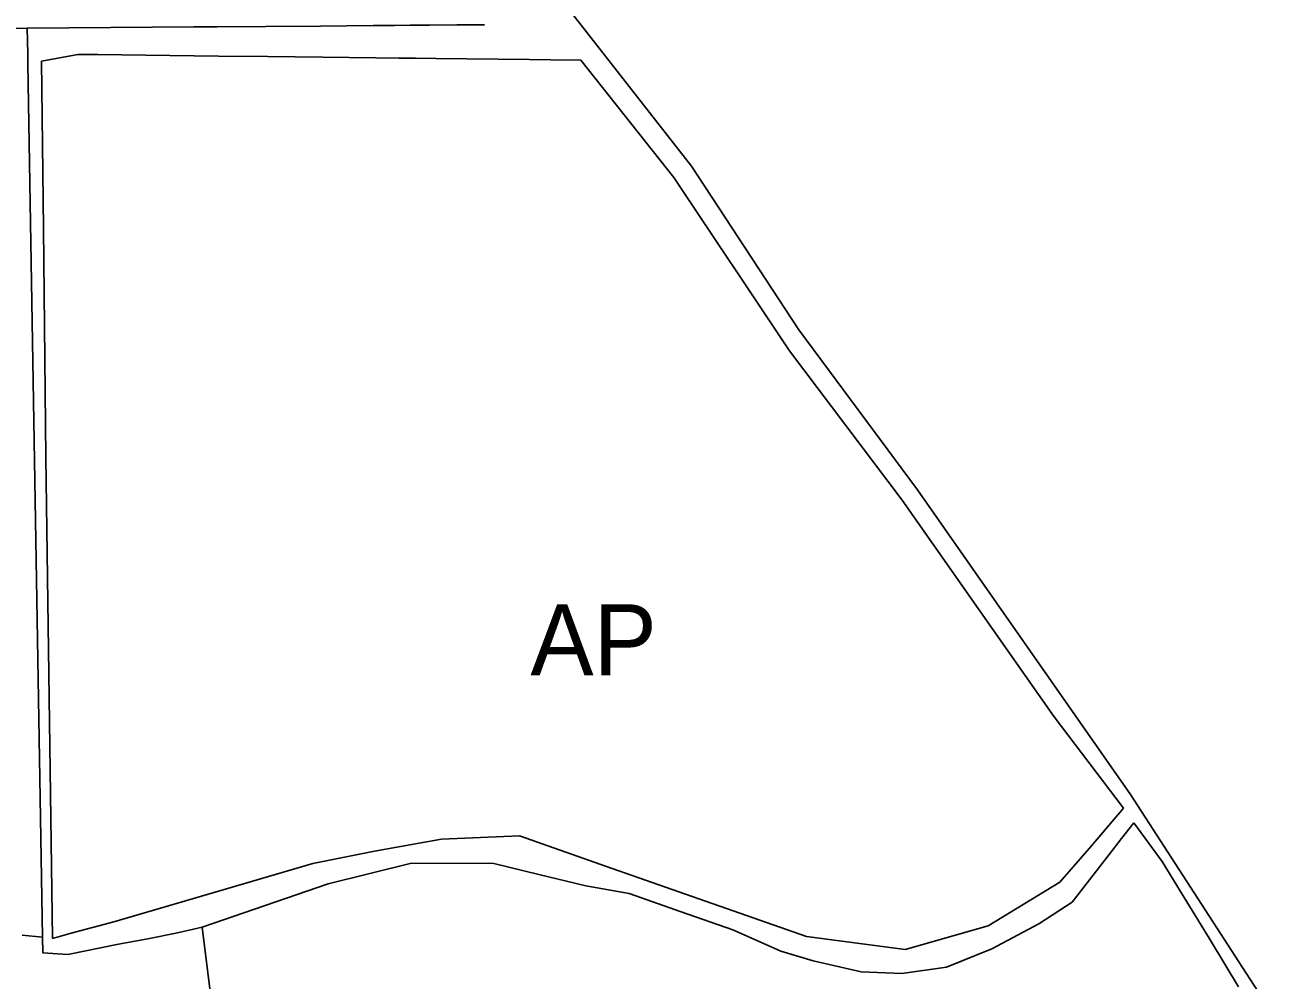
# Model space of a CAD drawing. Extents: x -555509 to -553005, y -1186756 to -1182560.
# Drawn here: x -553299.5 to -553054.5, y -1185330.3 to -1185141.6 of the extents above; entities that cross this region are included whole.
import ezdxf

# ---------------------------------------------------------------- set-up
doc = ezdxf.new("R2010")
doc.units = 0
for name, color, linetype in [('Level 26', 7, 'Continuous'), ('Level 59', 7, 'Continuous'), ('OBRYS_PLOCH', 7, 'Continuous'), ('stav_AP', 7, 'Continuous'), ('stav_ZK', 7, 'Continuous')]:
    doc.layers.add(name, color=color, linetype=linetype)

msp = doc.modelspace()

# ---------------------------------------------------------------- linework, layer by layer
at = {"layer": 'Level 26'}
for p, q in [((-553167.79, -1185169.52), (-553192, -1185138.59)), ((-553266.13, -1185142), (-553299.05, -1185142.26)), ((-553261.52, -1185141.96), (-553266.13, -1185142)), ((-553251.91, -1185141.89), (-553261.52, -1185141.96)), ((-553241.09, -1185141.81), (-553251.91, -1185141.89)), ((-553230.72, -1185141.72), (-553241.09, -1185141.81)), ((-553226.53, -1185141.69), (-553230.72, -1185141.72)), ((-553223.43, -1185141.67), (-553226.53, -1185141.69)), ((-553219.59, -1185141.64), (-553223.43, -1185141.67)), ((-553214.16, -1185141.6), (-553219.59, -1185141.64)), ((-553208.75, -1185141.55), (-553214.16, -1185141.6)), ((-553299.05, -1185142.26), (-553298.97, -1185147.3)), ((-553298.97, -1185147.3), (-553298.94, -1185149.27)), ((-553298.94, -1185149.27), (-553296.05, -1185321.81)), ((-553296.22, -1185148.74), (-553289.09, -1185147.41)), ((-553295.86, -1185181.74), (-553296.22, -1185148.74)), ((-553289.09, -1185147.41), (-553285.12, -1185147.46)), ((-553285.12, -1185147.46), (-553270.87, -1185147.63)), ((-553270.87, -1185147.63), (-553261.25, -1185147.74)), ((-553261.25, -1185147.74), (-553251.59, -1185147.85)), ((-553251.59, -1185147.85), (-553240.69, -1185147.98)), ((-553240.69, -1185147.98), (-553230.18, -1185148.1)), ((-553230.18, -1185148.1), (-553225.64, -1185148.15)), ((-553225.64, -1185148.15), (-553222.32, -1185148.19)), ((-553222.32, -1185148.19), (-553218.32, -1185148.24)), ((-553218.32, -1185148.24), (-553212.29, -1185148.31)), ((-553212.29, -1185148.31), (-553206.02, -1185148.38)), ((-553206.02, -1185148.38), (-553199.8, -1185148.45)), ((-553199.8, -1185148.45), (-553195.59, -1185148.5)), ((-553195.59, -1185148.5), (-553189.66, -1185148.57)), ((-553189.66, -1185148.57), (-553171.28, -1185171.74)), ((-553146.64, -1185201.83), (-553167.79, -1185169.52)), ((-553171.28, -1185171.74), (-553148.46, -1185205.95)), ((-553295.36, -1185226.96), (-553295.86, -1185181.74)), ((-553123.18, -1185233.43), (-553146.64, -1185201.83)), ((-553148.46, -1185205.95), (-553126.2, -1185235.48)), ((-553294.06, -1185322.01), (-553295.36, -1185226.96)), ((-553081.09, -1185293.58), (-553123.18, -1185233.43)), ((-553126.2, -1185235.48), (-553096.2, -1185278.25)), ((-553096.2, -1185278.25), (-553082.5, -1185296.28)), ((-553054.48, -1185334.7), (-553081.09, -1185293.58)), ((-553082.5, -1185296.28), (-553088.81, -1185303.71)), ((-553082.87, -1185302.3), (-553080.44, -1185299.18)), ((-553080.44, -1185299.18), (-553074.85, -1185306.8)), ((-553217.23, -1185302.42), (-553230.42, -1185304.78)), ((-553201.82, -1185301.77), (-553217.23, -1185302.42)), ((-553183.47, -1185308.24), (-553201.82, -1185301.77)), ((-553088.81, -1185303.71), (-553095.04, -1185310.94)), ((-553085.32, -1185305.43), (-553082.87, -1185302.3)), ((-553230.42, -1185304.78), (-553242.66, -1185307.22)), ((-553092.62, -1185314.88), (-553085.32, -1185305.43)), ((-553242.66, -1185307.22), (-553253.65, -1185310.44)), ((-553239.61, -1185311.26), (-553223.12, -1185307.13)), ((-553223.12, -1185307.13), (-553206.89, -1185307.24)), ((-553206.89, -1185307.24), (-553198, -1185309.4)), ((-553145.08, -1185321.66), (-553183.47, -1185308.24)), ((-553074.85, -1185306.8), (-553070.46, -1185313.92)), ((-553253.65, -1185310.44), (-553264.63, -1185313.66)), ((-553198, -1185309.4), (-553188.72, -1185311.63)), ((-553095.04, -1185310.94), (-553109.2, -1185319.53)), ((-553264.49, -1185319.8), (-553239.61, -1185311.26)), ((-553188.72, -1185311.63), (-553180.12, -1185313.18)), ((-553180.12, -1185313.18), (-553169.88, -1185316.76)), ((-553264.63, -1185313.66), (-553281.96, -1185318.74)), ((-553099.19, -1185319.15), (-553092.62, -1185314.88)), ((-553070.46, -1185313.92), (-553065.55, -1185322)), ((-553169.88, -1185316.76), (-553159.63, -1185320.34)), ((-553281.96, -1185318.74), (-553290.41, -1185321.02)), ((-553275.26, -1185322.08), (-553269.35, -1185320.92)), ((-553269.35, -1185320.92), (-553264.49, -1185319.8)), ((-553159.63, -1185320.34), (-553150.16, -1185324.56)), ((-553109.2, -1185319.53), (-553125.61, -1185324.23)), ((-553108.51, -1185324.1), (-553099.19, -1185319.15)), ((-553296.05, -1185321.81), (-553296, -1185324.85)), ((-553290.41, -1185321.02), (-553294.06, -1185322.01)), ((-553291.05, -1185325.2), (-553281.02, -1185323.15)), ((-553281.02, -1185323.15), (-553275.26, -1185322.08)), ((-553125.61, -1185324.23), (-553145.08, -1185321.66)), ((-553065.55, -1185322), (-553062.27, -1185327.43)), ((-553296, -1185324.85), (-553291.05, -1185325.2)), ((-553150.16, -1185324.56), (-553143.77, -1185326.44)), ((-553117.46, -1185327.69), (-553108.51, -1185324.1)), ((-553143.77, -1185326.44), (-553134.31, -1185328.63)), ((-553126.26, -1185328.97), (-553117.46, -1185327.69)), ((-553062.27, -1185327.43), (-553059.75, -1185331.58)), ((-553134.31, -1185328.63), (-553126.26, -1185328.97))]:
    msp.add_line(p, q, dxfattribs=at)
at = {"layer": 'OBRYS_PLOCH'}
for p, q in [((-553167.79, -1185169.52), (-553192, -1185138.59)), ((-553266.13, -1185142), (-553299.05, -1185142.26)), ((-553261.52, -1185141.96), (-553266.13, -1185142)), ((-553251.91, -1185141.89), (-553261.52, -1185141.96)), ((-553241.09, -1185141.81), (-553251.91, -1185141.89)), ((-553230.72, -1185141.72), (-553241.09, -1185141.81)), ((-553226.53, -1185141.69), (-553230.72, -1185141.72)), ((-553223.43, -1185141.67), (-553226.53, -1185141.69)), ((-553219.59, -1185141.64), (-553223.43, -1185141.67)), ((-553214.16, -1185141.6), (-553219.59, -1185141.64)), ((-553208.75, -1185141.55), (-553214.16, -1185141.6)), ((-553299.05, -1185142.26), (-553303.58, -1185142.29)), ((-553298.97, -1185147.3), (-553299.05, -1185142.26)), ((-553299.05, -1185142.26), (-553298.97, -1185147.3)), ((-553298.94, -1185149.27), (-553298.97, -1185147.3)), ((-553298.97, -1185147.3), (-553298.94, -1185149.27)), ((-553296.05, -1185321.81), (-553298.94, -1185149.27)), ((-553298.94, -1185149.27), (-553296.05, -1185321.81)), ((-553296.22, -1185148.74), (-553289.09, -1185147.41)), ((-553289.09, -1185147.41), (-553296.22, -1185148.74)), ((-553295.86, -1185181.74), (-553296.22, -1185148.74)), ((-553296.22, -1185148.74), (-553295.86, -1185181.74)), ((-553289.09, -1185147.41), (-553285.12, -1185147.46)), ((-553285.12, -1185147.46), (-553289.09, -1185147.41)), ((-553285.12, -1185147.46), (-553270.87, -1185147.63)), ((-553270.87, -1185147.63), (-553285.12, -1185147.46)), ((-553270.87, -1185147.63), (-553261.25, -1185147.74)), ((-553261.25, -1185147.74), (-553270.87, -1185147.63)), ((-553261.25, -1185147.74), (-553251.59, -1185147.85)), ((-553251.59, -1185147.85), (-553261.25, -1185147.74)), ((-553251.59, -1185147.85), (-553240.69, -1185147.98)), ((-553240.69, -1185147.98), (-553251.59, -1185147.85)), ((-553240.69, -1185147.98), (-553230.18, -1185148.1)), ((-553230.18, -1185148.1), (-553240.69, -1185147.98)), ((-553230.18, -1185148.1), (-553225.64, -1185148.15)), ((-553225.64, -1185148.15), (-553230.18, -1185148.1)), ((-553225.64, -1185148.15), (-553222.32, -1185148.19)), ((-553222.32, -1185148.19), (-553225.64, -1185148.15)), ((-553222.32, -1185148.19), (-553218.32, -1185148.24)), ((-553218.32, -1185148.24), (-553222.32, -1185148.19)), ((-553218.32, -1185148.24), (-553212.29, -1185148.31)), ((-553212.29, -1185148.31), (-553218.32, -1185148.24)), ((-553212.29, -1185148.31), (-553206.02, -1185148.38)), ((-553206.02, -1185148.38), (-553212.29, -1185148.31)), ((-553206.02, -1185148.38), (-553199.8, -1185148.45)), ((-553199.8, -1185148.45), (-553206.02, -1185148.38)), ((-553199.8, -1185148.45), (-553195.59, -1185148.5)), ((-553195.59, -1185148.5), (-553199.8, -1185148.45)), ((-553195.59, -1185148.5), (-553189.66, -1185148.57)), ((-553189.66, -1185148.57), (-553195.59, -1185148.5)), ((-553189.66, -1185148.57), (-553171.28, -1185171.74)), ((-553171.28, -1185171.74), (-553189.66, -1185148.57)), ((-553146.64, -1185201.83), (-553167.79, -1185169.52)), ((-553171.28, -1185171.74), (-553148.46, -1185205.95)), ((-553148.46, -1185205.95), (-553171.28, -1185171.74)), ((-553295.36, -1185226.96), (-553295.86, -1185181.74)), ((-553295.86, -1185181.74), (-553295.36, -1185226.96)), ((-553123.18, -1185233.43), (-553146.64, -1185201.83)), ((-553148.46, -1185205.95), (-553126.2, -1185235.48)), ((-553126.2, -1185235.48), (-553148.46, -1185205.95)), ((-553294.06, -1185322.01), (-553295.36, -1185226.96)), ((-553295.36, -1185226.96), (-553294.06, -1185322.01)), ((-553081.09, -1185293.58), (-553123.18, -1185233.43)), ((-553126.2, -1185235.48), (-553096.2, -1185278.25)), ((-553096.2, -1185278.25), (-553126.2, -1185235.48)), ((-553096.2, -1185278.25), (-553082.5, -1185296.28)), ((-553082.5, -1185296.28), (-553096.2, -1185278.25)), ((-553054.48, -1185334.7), (-553081.09, -1185293.58)), ((-553082.5, -1185296.28), (-553088.81, -1185303.71)), ((-553088.81, -1185303.71), (-553082.5, -1185296.28)), ((-553080.44, -1185299.18), (-553082.87, -1185302.3)), ((-553082.87, -1185302.3), (-553080.44, -1185299.18)), ((-553074.85, -1185306.8), (-553080.44, -1185299.18)), ((-553080.44, -1185299.18), (-553074.85, -1185306.8)), ((-553217.23, -1185302.42), (-553230.42, -1185304.78)), ((-553230.42, -1185304.78), (-553217.23, -1185302.42)), ((-553201.82, -1185301.77), (-553217.23, -1185302.42)), ((-553217.23, -1185302.42), (-553201.82, -1185301.77)), ((-553183.47, -1185308.24), (-553201.82, -1185301.77)), ((-553201.82, -1185301.77), (-553183.47, -1185308.24)), ((-553088.81, -1185303.71), (-553095.04, -1185310.94)), ((-553095.04, -1185310.94), (-553088.81, -1185303.71)), ((-553082.87, -1185302.3), (-553085.32, -1185305.43)), ((-553085.32, -1185305.43), (-553082.87, -1185302.3)), ((-553230.42, -1185304.78), (-553242.66, -1185307.22)), ((-553242.66, -1185307.22), (-553230.42, -1185304.78)), ((-553085.32, -1185305.43), (-553092.62, -1185314.88)), ((-553092.62, -1185314.88), (-553085.32, -1185305.43)), ((-553242.66, -1185307.22), (-553253.65, -1185310.44)), ((-553253.65, -1185310.44), (-553242.66, -1185307.22)), ((-553223.12, -1185307.13), (-553239.61, -1185311.26)), ((-553239.61, -1185311.26), (-553223.12, -1185307.13)), ((-553206.89, -1185307.24), (-553223.12, -1185307.13)), ((-553223.12, -1185307.13), (-553206.89, -1185307.24)), ((-553198, -1185309.4), (-553206.89, -1185307.24)), ((-553206.89, -1185307.24), (-553198, -1185309.4)), ((-553145.08, -1185321.66), (-553183.47, -1185308.24)), ((-553183.47, -1185308.24), (-553145.08, -1185321.66)), ((-553070.46, -1185313.92), (-553074.85, -1185306.8)), ((-553074.85, -1185306.8), (-553070.46, -1185313.92)), ((-553253.65, -1185310.44), (-553264.63, -1185313.66)), ((-553264.63, -1185313.66), (-553253.65, -1185310.44)), ((-553188.72, -1185311.63), (-553198, -1185309.4)), ((-553198, -1185309.4), (-553188.72, -1185311.63)), ((-553095.04, -1185310.94), (-553109.2, -1185319.53)), ((-553109.2, -1185319.53), (-553095.04, -1185310.94)), ((-553239.61, -1185311.26), (-553264.49, -1185319.8)), ((-553264.49, -1185319.8), (-553239.61, -1185311.26)), ((-553180.12, -1185313.18), (-553188.72, -1185311.63)), ((-553188.72, -1185311.63), (-553180.12, -1185313.18)), ((-553169.88, -1185316.76), (-553180.12, -1185313.18)), ((-553180.12, -1185313.18), (-553169.88, -1185316.76)), ((-553264.63, -1185313.66), (-553281.96, -1185318.74)), ((-553281.96, -1185318.74), (-553264.63, -1185313.66)), ((-553092.62, -1185314.88), (-553099.19, -1185319.15)), ((-553099.19, -1185319.15), (-553092.62, -1185314.88)), ((-553065.55, -1185322), (-553070.46, -1185313.92)), ((-553070.46, -1185313.92), (-553065.55, -1185322)), ((-553159.63, -1185320.34), (-553169.88, -1185316.76)), ((-553169.88, -1185316.76), (-553159.63, -1185320.34)), ((-553281.96, -1185318.74), (-553290.41, -1185321.02)), ((-553290.41, -1185321.02), (-553281.96, -1185318.74)), ((-553275.26, -1185322.08), (-553269.35, -1185320.92)), ((-553269.35, -1185320.92), (-553264.49, -1185319.8)), ((-553264.49, -1185319.8), (-553262.65, -1185334.59)), ((-553150.16, -1185324.56), (-553159.63, -1185320.34)), ((-553159.63, -1185320.34), (-553150.16, -1185324.56)), ((-553109.2, -1185319.53), (-553125.61, -1185324.23)), ((-553125.61, -1185324.23), (-553109.2, -1185319.53)), ((-553099.19, -1185319.15), (-553108.51, -1185324.1)), ((-553108.51, -1185324.1), (-553099.19, -1185319.15)), ((-553300.03, -1185321.4), (-553296.05, -1185321.81)), ((-553296.05, -1185321.81), (-553296, -1185324.85)), ((-553290.41, -1185321.02), (-553294.06, -1185322.01)), ((-553294.06, -1185322.01), (-553290.41, -1185321.02)), ((-553291.05, -1185325.2), (-553281.02, -1185323.15)), ((-553281.02, -1185323.15), (-553275.26, -1185322.08)), ((-553125.61, -1185324.23), (-553145.08, -1185321.66)), ((-553145.08, -1185321.66), (-553125.61, -1185324.23)), ((-553062.27, -1185327.43), (-553065.55, -1185322)), ((-553065.55, -1185322), (-553062.27, -1185327.43)), ((-553296, -1185324.85), (-553291.05, -1185325.2)), ((-553143.77, -1185326.44), (-553150.16, -1185324.56)), ((-553150.16, -1185324.56), (-553143.77, -1185326.44)), ((-553108.51, -1185324.1), (-553117.46, -1185327.69)), ((-553117.46, -1185327.69), (-553108.51, -1185324.1)), ((-553134.31, -1185328.63), (-553143.77, -1185326.44)), ((-553143.77, -1185326.44), (-553134.31, -1185328.63)), ((-553117.46, -1185327.69), (-553126.26, -1185328.97)), ((-553126.26, -1185328.97), (-553117.46, -1185327.69)), ((-553059.75, -1185331.58), (-553062.27, -1185327.43)), ((-553062.27, -1185327.43), (-553059.75, -1185331.58)), ((-553126.26, -1185328.97), (-553134.31, -1185328.63)), ((-553134.31, -1185328.63), (-553126.26, -1185328.97))]:
    msp.add_line(p, q, dxfattribs=at)
for points in [[(-553303.58, -1185142.29), (-553299.05, -1185142.26), (-553266.13, -1185142), (-553261.52, -1185141.96), (-553251.91, -1185141.89), (-553241.09, -1185141.81), (-553230.72, -1185141.72), (-553226.53, -1185141.69), (-553223.43, -1185141.67), (-553219.59, -1185141.64), (-553214.16, -1185141.6), (-553208.75, -1185141.55)], [(-553301.98, -1185455.8), (-553295.66, -1185456.88), (-553288.83, -1185457.78), (-553281.1, -1185460.35), (-553272.32, -1185460), (-553259.44, -1185455.69), (-553255.11, -1185454.24), (-553250.37, -1185452.65), (-553253.41, -1185417.54), (-553255.21, -1185402.3), (-553257.14, -1185387.15), (-553259.05, -1185371.88), (-553259.87, -1185356.41), (-553262.65, -1185334.59), (-553264.49, -1185319.8), (-553269.35, -1185320.92), (-553275.26, -1185322.08), (-553281.02, -1185323.15), (-553291.05, -1185325.2), (-553296, -1185324.85), (-553296.05, -1185321.81), (-553300.03, -1185321.4)]]:
    msp.add_lwpolyline(points, dxfattribs=at)
at = {"layer": 'stav_AP'}
for p, q in [((-553289.09, -1185147.41), (-553296.22, -1185148.74)), ((-553296.22, -1185148.74), (-553295.86, -1185181.74)), ((-553285.12, -1185147.46), (-553289.09, -1185147.41)), ((-553270.87, -1185147.63), (-553285.12, -1185147.46)), ((-553261.25, -1185147.74), (-553270.87, -1185147.63)), ((-553251.59, -1185147.85), (-553261.25, -1185147.74)), ((-553240.69, -1185147.98), (-553251.59, -1185147.85)), ((-553230.18, -1185148.1), (-553240.69, -1185147.98)), ((-553225.64, -1185148.15), (-553230.18, -1185148.1)), ((-553222.32, -1185148.19), (-553225.64, -1185148.15)), ((-553218.32, -1185148.24), (-553222.32, -1185148.19)), ((-553212.29, -1185148.31), (-553218.32, -1185148.24)), ((-553206.02, -1185148.38), (-553212.29, -1185148.31)), ((-553199.8, -1185148.45), (-553206.02, -1185148.38)), ((-553195.59, -1185148.5), (-553199.8, -1185148.45)), ((-553189.66, -1185148.57), (-553195.59, -1185148.5)), ((-553171.28, -1185171.74), (-553189.66, -1185148.57)), ((-553148.46, -1185205.95), (-553171.28, -1185171.74)), ((-553295.86, -1185181.74), (-553295.36, -1185226.96)), ((-553126.2, -1185235.48), (-553148.46, -1185205.95)), ((-553295.36, -1185226.96), (-553294.06, -1185322.01)), ((-553096.2, -1185278.25), (-553126.2, -1185235.48)), ((-553082.5, -1185296.28), (-553096.2, -1185278.25)), ((-553088.81, -1185303.71), (-553082.5, -1185296.28)), ((-553230.42, -1185304.78), (-553217.23, -1185302.42)), ((-553217.23, -1185302.42), (-553201.82, -1185301.77)), ((-553201.82, -1185301.77), (-553183.47, -1185308.24)), ((-553095.04, -1185310.94), (-553088.81, -1185303.71)), ((-553242.66, -1185307.22), (-553230.42, -1185304.78)), ((-553253.65, -1185310.44), (-553242.66, -1185307.22)), ((-553183.47, -1185308.24), (-553145.08, -1185321.66)), ((-553264.63, -1185313.66), (-553253.65, -1185310.44)), ((-553109.2, -1185319.53), (-553095.04, -1185310.94)), ((-553281.96, -1185318.74), (-553264.63, -1185313.66)), ((-553290.41, -1185321.02), (-553281.96, -1185318.74)), ((-553125.61, -1185324.23), (-553109.2, -1185319.53)), ((-553294.06, -1185322.01), (-553290.41, -1185321.02)), ((-553145.08, -1185321.66), (-553125.61, -1185324.23))]:
    msp.add_line(p, q, dxfattribs=at)
for points in [[(-553303.58, -1185142.29), (-553299.05, -1185142.26), (-553266.13, -1185142), (-553261.52, -1185141.96), (-553251.91, -1185141.89), (-553241.09, -1185141.81), (-553230.72, -1185141.72), (-553226.53, -1185141.69), (-553223.43, -1185141.67), (-553219.59, -1185141.64), (-553214.16, -1185141.6), (-553208.75, -1185141.55)], [(-553301.98, -1185455.8), (-553295.66, -1185456.88), (-553288.83, -1185457.78), (-553281.1, -1185460.35), (-553272.32, -1185460), (-553259.44, -1185455.69), (-553255.11, -1185454.24), (-553250.37, -1185452.65), (-553253.41, -1185417.54), (-553255.21, -1185402.3), (-553257.14, -1185387.15), (-553259.05, -1185371.88), (-553259.87, -1185356.41), (-553262.65, -1185334.59), (-553264.49, -1185319.8), (-553269.35, -1185320.92), (-553275.26, -1185322.08), (-553281.02, -1185323.15), (-553291.05, -1185325.2), (-553296, -1185324.85), (-553296.05, -1185321.81), (-553300.03, -1185321.4)]]:
    msp.add_lwpolyline(points, dxfattribs=at)
at = {"layer": 'stav_ZK'}
for p, q in [((-553299.05, -1185142.26), (-553303.58, -1185142.29)), ((-553298.97, -1185147.3), (-553299.05, -1185142.26)), ((-553298.94, -1185149.27), (-553298.97, -1185147.3)), ((-553296.05, -1185321.81), (-553298.94, -1185149.27)), ((-553080.44, -1185299.18), (-553082.87, -1185302.3)), ((-553074.85, -1185306.8), (-553080.44, -1185299.18)), ((-553082.87, -1185302.3), (-553085.32, -1185305.43)), ((-553085.32, -1185305.43), (-553092.62, -1185314.88)), ((-553223.12, -1185307.13), (-553239.61, -1185311.26)), ((-553206.89, -1185307.24), (-553223.12, -1185307.13)), ((-553198, -1185309.4), (-553206.89, -1185307.24)), ((-553070.46, -1185313.92), (-553074.85, -1185306.8)), ((-553188.72, -1185311.63), (-553198, -1185309.4)), ((-553239.61, -1185311.26), (-553264.49, -1185319.8)), ((-553180.12, -1185313.18), (-553188.72, -1185311.63)), ((-553169.88, -1185316.76), (-553180.12, -1185313.18)), ((-553092.62, -1185314.88), (-553099.19, -1185319.15)), ((-553065.55, -1185322), (-553070.46, -1185313.92)), ((-553159.63, -1185320.34), (-553169.88, -1185316.76)), ((-553264.49, -1185319.8), (-553262.65, -1185334.59)), ((-553150.16, -1185324.56), (-553159.63, -1185320.34)), ((-553099.19, -1185319.15), (-553108.51, -1185324.1)), ((-553300.03, -1185321.4), (-553296.05, -1185321.81)), ((-553062.27, -1185327.43), (-553065.55, -1185322)), ((-553143.77, -1185326.44), (-553150.16, -1185324.56)), ((-553108.51, -1185324.1), (-553117.46, -1185327.69)), ((-553134.31, -1185328.63), (-553143.77, -1185326.44)), ((-553117.46, -1185327.69), (-553126.26, -1185328.97)), ((-553059.75, -1185331.58), (-553062.27, -1185327.43)), ((-553126.26, -1185328.97), (-553134.31, -1185328.63))]:
    msp.add_line(p, q, dxfattribs=at)

# ---------------------------------------------------------------- texts
at = {"layer": 'Level 59'}
msp.add_text('AP', height=14, dxfattribs=at).set_placement((-553199.65, -1185270.03))

doc.saveas('drawing.dxf')
